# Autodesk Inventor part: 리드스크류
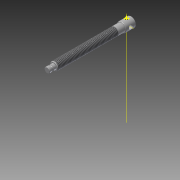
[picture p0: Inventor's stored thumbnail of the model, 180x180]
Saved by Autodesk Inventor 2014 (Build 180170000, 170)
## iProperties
Created: 2019-04
Part Number: 리드스크류
Material: 강철, 연강
Document SubType Name: Modeling
Designer: mduedu
Density: 1 g/cm^3
Appearance: Steel
Author: mduedu
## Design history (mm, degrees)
sketch "스케치1"
  geometry: C1 r 6 at (0, 0); 1 further point
  constraints: 1 centre point, 1 coincident
  dimensions: "d0" = 12 diameter of C1
extrude "돌출1" new body sketch "스케치1" distance "d1" = 100; taper "d2" = 0 deg
sketch "스케치2"
  geometry: C1 r 4 at (0, 0); 1 further point
  constraints: 1 centre point, 1 coincident
  dimensions: "d3" = 8 diameter of C1
extrude "돌출2" join sketch "스케치2" distance "d4" = 10; taper "d5" = 0 deg
sketch "스케치3"
  geometry: C1 r 7 at (0, 0); 1 further point
  constraints: 1 centre point, 1 coincident
  dimensions: "d9" = 14 diameter of C1
extrude "돌출3" join sketch "스케치3" distance "d10" = 15; taper "d11" = 0 deg
feature "스레드1" dims "d12" = 90, "d13" = 0
chamfer "모따기2" distance "d14" = 1; stored, may be unused: second distance "d15" = 2, angle "d16" = 45 deg
chamfer "모따기3" distance "d17" = 0.5; stored, may be unused: second distance "d18" = 2, angle "d19" = 45 deg
chamfer "모따기4" distance "d20" = 0.5; stored, may be unused: second distance "d21" = 2, angle "d22" = 45 deg
sketch "스케치4"
  geometry: L1 (-100, -5)-(-100, 5) reference; L2 (-109.5, 4)-(-109.5, -4) reference; L3 (-109.5, 0)-(-100, 0); C1 r 1.25 at (-105, 4); 1 further point
  constraints: 2 end point, 2 midpoint, 1 centre point
  dimensions: "d23" = 2.5 diameter of C1; "d24" = 5 distance from line of C1.centre L1; "d25" = 4 distance from line of C1.centre L3
revolve "회전1" sketch "스케치4" stored, may be unused: angle "d26" = 90 deg
sketch "스케치5"
  geometry: L1 (0, -6.5)-(0, 6.5) reference; C1 r 3 at (7.5, 0); 2 further points
  constraints: 1 centre point, 1 horizontal alignment, 1 midpoint
  dimensions: "d27" = 6 diameter of C1; "d28" = 7.5 distance from line of C1.centre L1
extrude "돌출4" cut sketch "스케치5" stored distance "d29" = 15; taper "d30" = 0 deg
node "작업 평면1"
sketch "스케치6"
  geometry: L1 (0, 6.5)-(0, -6.5) reference; 2 further points
  constraints: 1 horizontal alignment
  dimensions: "d31" = 7.5 distance from line of point (-7.5, 0) L1
hole "구멍1" sketch "스케치6" at (-7.5, 0) diameter "d32" = 3.242; stored, may be unused: countersink angle "d36" = 90 deg, drill point angle "d38" = 118 deg; dims "d33" = 6, "d34" = 4, "d35" = 2, "d37" = 8
workaxis "Work Axis1"
workpoint "Work Point1"
  workaxis "Work Axis2"
node "솔리드1"
